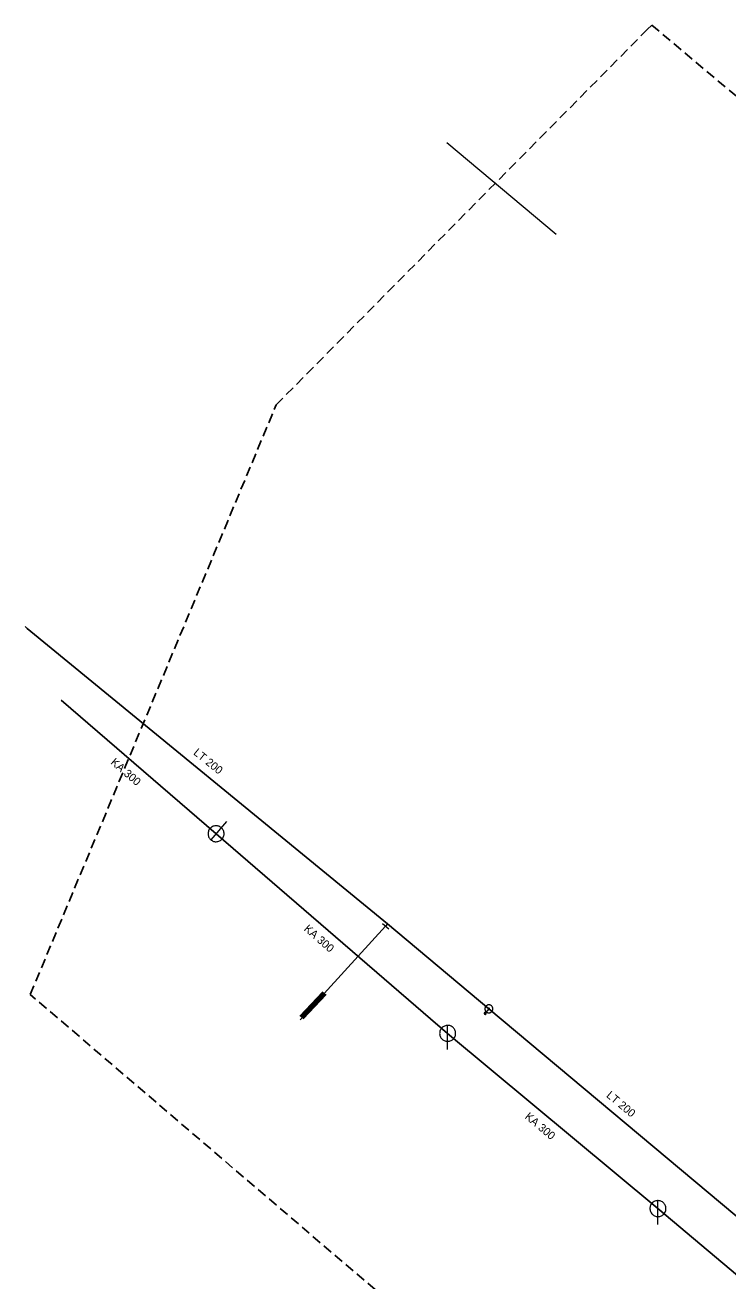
# Model space of a CAD drawing. Extents: x -790267 to -789874, y -989766 to -989454.
# Drawn here: x -790266.7 to -790179, y -989612.1 to -989455.1 of the extents above; entities that cross this region are included whole.
import ezdxf

# ---------------------------------------------------------------- set-up
doc = ezdxf.new("R2010")
doc.units = 0
doc.header["$LTSCALE"] = 0.4
doc.linetypes.add('MEDIUM_DASHED', pattern=[4.5, 3, -1.5])
doc.layers.add('1', color=7, linetype='Continuous')
for name, color, linetype, lineweight in [('13', 7, 'Continuous', 13), ('14', 7, 'Continuous', 13), ('17', 7, 'Continuous', 25), ('22', 7, 'Continuous', 13), ('3', 7, 'Continuous', 106), ('34', 7, 'Continuous', 13), ('47', 7, 'Continuous', 13), ('63', 7, 'MEDIUM_DASHED', 25), ('9', 7, 'Continuous', 13)]:
    doc.layers.add(name, color=color, linetype=linetype, lineweight=lineweight)

msp = doc.modelspace()

# ---------------------------------------------------------------- linework, layer by layer
at = {"layer": '13'}
for p, q in [((-790214.037, -989469.794), (-790200.396, -989481.26)), ((-790221.697, -989567.736), (-790232.379, -989579.425))]:
    msp.add_line(p, q, dxfattribs=at)
at = {"layer": '14'}
for p, q in [((-790221.46, -989567.445), (-790221.697, -989567.736)), ((-790208.807, -989578.056), (-790209.259, -989578.62))]:
    msp.add_line(p, q, dxfattribs=at)
at = {"layer": '14', "lineweight": 25}
msp.add_line((-790187.694, -989603.019), (-790213.954, -989581.125), dxfattribs=at)
for points in [[(-790213.954, -989581.125), (-790242.87, -989556.179), (-790262.214, -989539.492)], [(-790061.947, -989710.475), (-790095.515, -989680.27), (-790099.671, -989676.98), (-790135.954, -989646.924), (-790158.92, -989627.239), (-790187.694, -989603.019)]]:
    msp.add_lwpolyline(points, dxfattribs=at)
at = {"layer": '17'}
msp.add_line((-790208.807, -989578.056), (-790176.305, -989605.314), dxfattribs=at)
msp.add_lwpolyline([(-790266.706, -989530.283), (-790266.449, -989530.55), (-790221.46, -989567.445), (-790208.807, -989578.056)], dxfattribs=at)
at = {"layer": '22'}
for p, q in [((-790241.563, -989554.664), (-790243.522, -989556.935)), ((-790213.954, -989583.125), (-790213.953, -989580.125)), ((-790187.694, -989605.019), (-790187.693, -989602.019))]:
    msp.add_line(p, q, dxfattribs=at)
for points in [[(-790243.626, -989555.525), (-790243.693, -989555.611), (-790243.75, -989555.705), (-790243.796, -989555.805), (-790243.832, -989555.907), (-790243.856, -989556.015), (-790243.868, -989556.123), (-790243.868, -989556.233), (-790243.855, -989556.342), (-790243.832, -989556.449), (-790243.797, -989556.552), (-790243.75, -989556.651), (-790243.692, -989556.745), (-790243.626, -989556.832), (-790243.55, -989556.91), (-790243.465, -989556.981), (-790243.374, -989557.041), (-790243.277, -989557.092), (-790243.175, -989557.131), (-790243.068, -989557.158), (-790242.961, -989557.174), (-790242.851, -989557.178), (-790242.742, -989557.17), (-790242.634, -989557.15), (-790242.529, -989557.119), (-790242.429, -989557.076), (-790242.333, -989557.022), (-790242.244, -989556.958), (-790242.163, -989556.885), (-790242.089, -989556.803), (-790242.026, -989556.714), (-790241.972, -989556.62), (-790241.929, -989556.519), (-790241.897, -989556.414), (-790241.877, -989556.306), (-790241.87, -989556.197), (-790241.873, -989556.088), (-790241.889, -989555.979), (-790241.917, -989555.873), (-790241.955, -989555.771), (-790242.006, -989555.673), (-790242.066, -989555.582), (-790242.136, -989555.498), (-790242.215, -989555.422), (-790242.302, -989555.355), (-790242.395, -989555.298), (-790242.494, -989555.251), (-790242.598, -989555.216), (-790242.705, -989555.192), (-790242.814, -989555.18), (-790242.923, -989555.18), (-790243.032, -989555.191), (-790243.139, -989555.215), (-790243.242, -989555.25), (-790243.341, -989555.297), (-790243.435, -989555.353), (-790243.522, -989555.421), (-790243.601, -989555.497)], [(-790212.954, -989581.125), (-790212.959, -989581.016), (-790212.977, -989580.908), (-790213.007, -989580.802), (-790213.047, -989580.701), (-790213.099, -989580.604), (-790213.161, -989580.514), (-790213.233, -989580.431), (-790213.313, -989580.357), (-790213.401, -989580.291), (-790213.495, -989580.236), (-790213.595, -989580.191), (-790213.7, -989580.158), (-790213.807, -989580.136), (-790213.916, -989580.126), (-790214.026, -989580.128), (-790214.134, -989580.142), (-790214.241, -989580.167), (-790214.344, -989580.204), (-790214.442, -989580.253), (-790214.534, -989580.311), (-790214.62, -989580.38), (-790214.697, -989580.457), (-790214.766, -989580.543), (-790214.825, -989580.635), (-790214.873, -989580.733), (-790214.91, -989580.836), (-790214.936, -989580.943), (-790214.95, -989581.051), (-790214.953, -989581.161), (-790214.943, -989581.27), (-790214.922, -989581.377), (-790214.888, -989581.481), (-790214.844, -989581.581), (-790214.789, -989581.676), (-790214.723, -989581.764), (-790214.649, -989581.844), (-790214.566, -989581.916), (-790214.476, -989581.978), (-790214.38, -989582.03), (-790214.278, -989582.071), (-790214.173, -989582.101), (-790214.065, -989582.119), (-790213.955, -989582.125), (-790213.846, -989582.119), (-790213.738, -989582.101), (-790213.633, -989582.072), (-790213.531, -989582.031), (-790213.434, -989581.979), (-790213.344, -989581.917), (-790213.261, -989581.846), (-790213.186, -989581.766), (-790213.121, -989581.678), (-790213.065, -989581.584), (-790213.021, -989581.484), (-790212.987, -989581.38), (-790212.965, -989581.272), (-790212.955, -989581.163)], [(-790186.694, -989603.019), (-790186.699, -989602.91), (-790186.717, -989602.802), (-790186.747, -989602.696), (-790186.787, -989602.595), (-790186.839, -989602.498), (-790186.901, -989602.408), (-790186.973, -989602.325), (-790187.053, -989602.251), (-790187.141, -989602.185), (-790187.235, -989602.13), (-790187.335, -989602.085), (-790187.44, -989602.052), (-790187.547, -989602.03), (-790187.656, -989602.02), (-790187.766, -989602.022), (-790187.874, -989602.036), (-790187.981, -989602.061), (-790188.084, -989602.098), (-790188.182, -989602.147), (-790188.274, -989602.205), (-790188.36, -989602.274), (-790188.437, -989602.351), (-790188.506, -989602.437), (-790188.565, -989602.529), (-790188.613, -989602.627), (-790188.65, -989602.73), (-790188.676, -989602.837), (-790188.69, -989602.945), (-790188.693, -989603.055), (-790188.683, -989603.164), (-790188.662, -989603.271), (-790188.628, -989603.375), (-790188.584, -989603.475), (-790188.529, -989603.57), (-790188.463, -989603.658), (-790188.389, -989603.738), (-790188.306, -989603.81), (-790188.216, -989603.872), (-790188.12, -989603.924), (-790188.018, -989603.965), (-790187.913, -989603.995), (-790187.805, -989604.013), (-790187.695, -989604.019), (-790187.586, -989604.013), (-790187.478, -989603.995), (-790187.373, -989603.966), (-790187.271, -989603.925), (-790187.174, -989603.873), (-790187.084, -989603.811), (-790187.001, -989603.74), (-790186.926, -989603.66), (-790186.861, -989603.572), (-790186.805, -989603.478), (-790186.761, -989603.378), (-790186.727, -989603.274), (-790186.705, -989603.166), (-790186.695, -989603.057)]]:
    msp.add_lwpolyline(points, close=True, dxfattribs=at)
at = {"layer": '3'}
msp.add_line((-790229.329, -989576.088), (-790232.2, -989579.14), dxfattribs=at)
at = {"layer": '3', "lineweight": 100}
msp.add_line((-790229.329, -989576.088), (-790232.2, -989579.14), dxfattribs=at)
at = {"layer": '34'}
msp.add_line((-790222.078, -989567.412), (-790221.316, -989568.06), dxfattribs=at)
at = {"layer": '47'}
for points in [[(-790208.419, -989578.372), (-790208.389, -989578.329), (-790208.362, -989578.284), (-790208.341, -989578.237), (-790208.324, -989578.187), (-790208.313, -989578.136), (-790208.308, -989578.083), (-790208.308, -989578.031), (-790208.313, -989577.979), (-790208.323, -989577.928), (-790208.339, -989577.878), (-790208.36, -989577.83), (-790208.387, -989577.785), (-790208.417, -989577.742), (-790208.452, -989577.703), (-790208.49, -989577.668), (-790208.533, -989577.638), (-790208.578, -989577.611), (-790208.626, -989577.589), (-790208.675, -989577.573), (-790208.726, -989577.562), (-790208.779, -989577.557), (-790208.831, -989577.556), (-790208.884, -989577.562), (-790208.934, -989577.572), (-790208.984, -989577.588), (-790209.032, -989577.609), (-790209.078, -989577.635), (-790209.12, -989577.666), (-790209.159, -989577.701), (-790209.194, -989577.739), (-790209.224, -989577.782), (-790209.251, -989577.827), (-790209.273, -989577.875), (-790209.289, -989577.924), (-790209.3, -989577.975), (-790209.306, -989578.027), (-790209.307, -989578.08), (-790209.301, -989578.132), (-790209.29, -989578.183), (-790209.274, -989578.233), (-790209.253, -989578.281), (-790209.228, -989578.326), (-790209.196, -989578.369), (-790209.161, -989578.408), (-790209.123, -989578.443), (-790209.08, -989578.473), (-790209.035, -989578.5), (-790208.988, -989578.522), (-790208.938, -989578.538), (-790208.887, -989578.549), (-790208.835, -989578.555), (-790208.783, -989578.555), (-790208.731, -989578.55), (-790208.679, -989578.539), (-790208.629, -989578.523), (-790208.581, -989578.502), (-790208.537, -989578.476), (-790208.493, -989578.445), (-790208.454, -989578.41)], [(-790208.743, -989578.107), (-790208.737, -989578.1), (-790208.734, -989578.093), (-790208.73, -989578.085), (-790208.728, -989578.077), (-790208.726, -989578.069), (-790208.725, -989578.06), (-790208.724, -989578.051), (-790208.725, -989578.043), (-790208.728, -989578.035), (-790208.73, -989578.026), (-790208.734, -989578.018), (-790208.738, -989578.011), (-790208.743, -989578.004), (-790208.748, -989577.998), (-790208.755, -989577.992), (-790208.762, -989577.986), (-790208.769, -989577.983), (-790208.777, -989577.979), (-790208.785, -989577.977), (-790208.793, -989577.975), (-790208.802, -989577.974), (-790208.811, -989577.973), (-790208.819, -989577.974), (-790208.828, -989577.976), (-790208.836, -989577.979), (-790208.844, -989577.983), (-790208.851, -989577.987), (-790208.858, -989577.992), (-790208.864, -989577.997), (-790208.87, -989578.004), (-790208.876, -989578.011), (-790208.879, -989578.018), (-790208.883, -989578.026), (-790208.885, -989578.034), (-790208.887, -989578.042), (-790208.889, -989578.05), (-790208.889, -989578.06), (-790208.888, -989578.068), (-790208.886, -989578.077), (-790208.883, -989578.085), (-790208.879, -989578.093), (-790208.875, -989578.1), (-790208.87, -989578.107), (-790208.865, -989578.113), (-790208.858, -989578.119), (-790208.851, -989578.125), (-790208.844, -989578.128), (-790208.836, -989578.132), (-790208.828, -989578.134), (-790208.82, -989578.136), (-790208.812, -989578.138), (-790208.802, -989578.138), (-790208.794, -989578.137), (-790208.786, -989578.134), (-790208.777, -989578.132), (-790208.769, -989578.128), (-790208.762, -989578.124), (-790208.755, -989578.119), (-790208.749, -989578.114)]]:
    msp.add_lwpolyline(points, close=True, dxfattribs=at)
at = {"layer": '63'}
msp.add_lwpolyline([(-790188.469, -989455.136), (-790139.344, -989496.446), (-790139.344, -989496.446), (-790029.929, -989518.217), (-790029.929, -989518.217), (-789963.498, -989555.061), (-789963.498, -989555.061), (-789946.75, -989559.527), (-789946.75, -989559.527), (-789908.79, -989634.89), (-789908.79, -989634.89), (-790051.142, -989765.519), (-790051.142, -989765.519), (-790157.208, -989714.719), (-790157.208, -989714.719), (-790153.3, -989672.851), (-790153.3, -989672.851), (-790266.065, -989576.274), (-790266.065, -989576.274), (-790235.362, -989502.586), (-790235.362, -989502.586), (-790189.028, -989455.694), (-790189.028, -989455.694)], close=True, dxfattribs=at)
at = {"layer": '9'}
for points in [[(-790209.385, -989578.62), (-790209.385, -989578.633), (-790209.382, -989578.646), (-790209.38, -989578.659), (-790209.375, -989578.671), (-790209.369, -989578.683), (-790209.362, -989578.694), (-790209.353, -989578.704), (-790209.343, -989578.714), (-790209.333, -989578.722), (-790209.323, -989578.729), (-790209.311, -989578.735), (-790209.299, -989578.74), (-790209.286, -989578.743), (-790209.272, -989578.745), (-790209.26, -989578.747), (-790209.247, -989578.746), (-790209.233, -989578.744), (-790209.221, -989578.741), (-790209.208, -989578.736), (-790209.196, -989578.73), (-790209.186, -989578.723), (-790209.176, -989578.715), (-790209.166, -989578.705), (-790209.157, -989578.695), (-790209.151, -989578.684), (-790209.145, -989578.672), (-790209.14, -989578.66), (-790209.137, -989578.647), (-790209.135, -989578.634), (-790209.132, -989578.621), (-790209.134, -989578.608), (-790209.136, -989578.595), (-790209.139, -989578.582), (-790209.144, -989578.57), (-790209.149, -989578.558), (-790209.157, -989578.547), (-790209.164, -989578.537), (-790209.174, -989578.527), (-790209.184, -989578.519), (-790209.196, -989578.512), (-790209.208, -989578.506), (-790209.22, -989578.501), (-790209.233, -989578.498), (-790209.245, -989578.496), (-790209.259, -989578.495), (-790209.272, -989578.495), (-790209.284, -989578.497), (-790209.298, -989578.5), (-790209.309, -989578.505), (-790209.321, -989578.511), (-790209.333, -989578.518), (-790209.343, -989578.526), (-790209.353, -989578.536), (-790209.36, -989578.546), (-790209.368, -989578.557), (-790209.374, -989578.569), (-790209.379, -989578.581), (-790209.382, -989578.594), (-790209.384, -989578.607)], [(-790209.365, -989578.62), (-790209.365, -989578.631), (-790209.364, -989578.642), (-790209.36, -989578.653), (-790209.357, -989578.663), (-790209.352, -989578.673), (-790209.346, -989578.682), (-790209.338, -989578.691), (-790209.331, -989578.699), (-790209.321, -989578.706), (-790209.313, -989578.712), (-790209.303, -989578.717), (-790209.293, -989578.721), (-790209.282, -989578.724), (-790209.271, -989578.727), (-790209.26, -989578.727), (-790209.249, -989578.727), (-790209.238, -989578.725), (-790209.227, -989578.722), (-790209.217, -989578.718), (-790209.206, -989578.713), (-790209.198, -989578.707), (-790209.189, -989578.7), (-790209.181, -989578.692), (-790209.174, -989578.683), (-790209.168, -989578.674), (-790209.163, -989578.664), (-790209.159, -989578.654), (-790209.156, -989578.643), (-790209.154, -989578.632), (-790209.152, -989578.621), (-790209.152, -989578.61), (-790209.154, -989578.599), (-790209.157, -989578.588), (-790209.162, -989578.578), (-790209.167, -989578.568), (-790209.173, -989578.559), (-790209.179, -989578.55), (-790209.188, -989578.542), (-790209.196, -989578.535), (-790209.206, -989578.529), (-790209.216, -989578.524), (-790209.225, -989578.52), (-790209.237, -989578.517), (-790209.247, -989578.515), (-790209.259, -989578.515), (-790209.27, -989578.514), (-790209.281, -989578.516), (-790209.292, -989578.519), (-790209.301, -989578.523), (-790209.311, -989578.528), (-790209.321, -989578.534), (-790209.33, -989578.541), (-790209.338, -989578.549), (-790209.345, -989578.558), (-790209.35, -989578.567), (-790209.355, -989578.577), (-790209.36, -989578.587), (-790209.363, -989578.598), (-790209.365, -989578.609)], [(-790209.346, -989578.62), (-790209.346, -989578.629), (-790209.345, -989578.638), (-790209.342, -989578.647), (-790209.338, -989578.655), (-790209.335, -989578.663), (-790209.33, -989578.671), (-790209.323, -989578.678), (-790209.318, -989578.684), (-790209.311, -989578.69), (-790209.303, -989578.695), (-790209.294, -989578.699), (-790209.287, -989578.702), (-790209.277, -989578.705), (-790209.269, -989578.706), (-790209.26, -989578.708), (-790209.25, -989578.707), (-790209.242, -989578.706), (-790209.233, -989578.703), (-790209.225, -989578.7), (-790209.217, -989578.696), (-790209.208, -989578.691), (-790209.201, -989578.685), (-790209.196, -989578.679), (-790209.19, -989578.672), (-790209.184, -989578.664), (-790209.181, -989578.656), (-790209.178, -989578.648), (-790209.174, -989578.639), (-790209.174, -989578.63), (-790209.171, -989578.621), (-790209.173, -989578.612), (-790209.174, -989578.603), (-790209.176, -989578.594), (-790209.179, -989578.586), (-790209.184, -989578.578), (-790209.189, -989578.57), (-790209.195, -989578.563), (-790209.201, -989578.557), (-790209.208, -989578.551), (-790209.216, -989578.546), (-790209.223, -989578.542), (-790209.232, -989578.539), (-790209.24, -989578.536), (-790209.25, -989578.535), (-790209.259, -989578.534), (-790209.267, -989578.534), (-790209.277, -989578.535), (-790209.286, -989578.538), (-790209.294, -989578.541), (-790209.301, -989578.545), (-790209.309, -989578.55), (-790209.316, -989578.556), (-790209.323, -989578.562), (-790209.328, -989578.569), (-790209.333, -989578.577), (-790209.338, -989578.585), (-790209.341, -989578.593), (-790209.343, -989578.602), (-790209.345, -989578.611)], [(-790209.326, -989578.62), (-790209.326, -989578.627), (-790209.325, -989578.634), (-790209.323, -989578.641), (-790209.321, -989578.647), (-790209.318, -989578.653), (-790209.314, -989578.659), (-790209.309, -989578.665), (-790209.304, -989578.67), (-790209.299, -989578.674), (-790209.293, -989578.678), (-790209.287, -989578.681), (-790209.281, -989578.684), (-790209.274, -989578.685), (-790209.267, -989578.688), (-790209.26, -989578.688), (-790209.252, -989578.688), (-790209.245, -989578.686), (-790209.239, -989578.685), (-790209.233, -989578.682), (-790209.225, -989578.679), (-790209.221, -989578.675), (-790209.215, -989578.671), (-790209.21, -989578.666), (-790209.206, -989578.66), (-790209.201, -989578.654), (-790209.198, -989578.648), (-790209.196, -989578.642), (-790209.194, -989578.635), (-790209.193, -989578.628), (-790209.191, -989578.621), (-790209.191, -989578.614), (-790209.193, -989578.607), (-790209.195, -989578.6), (-790209.198, -989578.594), (-790209.201, -989578.587), (-790209.205, -989578.582), (-790209.208, -989578.576), (-790209.213, -989578.571), (-790209.22, -989578.567), (-790209.225, -989578.563), (-790209.232, -989578.56), (-790209.238, -989578.557), (-790209.245, -989578.555), (-790209.252, -989578.554), (-790209.259, -989578.554), (-790209.266, -989578.554), (-790209.272, -989578.554), (-790209.279, -989578.556), (-790209.286, -989578.559), (-790209.292, -989578.562), (-790209.298, -989578.566), (-790209.304, -989578.57), (-790209.309, -989578.575), (-790209.313, -989578.581), (-790209.316, -989578.586), (-790209.32, -989578.593), (-790209.323, -989578.599), (-790209.323, -989578.606), (-790209.326, -989578.613)], [(-790209.306, -989578.62), (-790209.306, -989578.625), (-790209.306, -989578.63), (-790209.304, -989578.635), (-790209.303, -989578.639), (-790209.301, -989578.644), (-790209.298, -989578.648), (-790209.294, -989578.651), (-790209.291, -989578.655), (-790209.288, -989578.658), (-790209.284, -989578.661), (-790209.279, -989578.663), (-790209.274, -989578.665), (-790209.27, -989578.666), (-790209.265, -989578.668), (-790209.26, -989578.668), (-790209.255, -989578.668), (-790209.25, -989578.667), (-790209.245, -989578.666), (-790209.24, -989578.664), (-790209.235, -989578.662), (-790209.232, -989578.659), (-790209.228, -989578.656), (-790209.225, -989578.652), (-790209.222, -989578.649), (-790209.218, -989578.645), (-790209.217, -989578.64), (-790209.215, -989578.636), (-790209.213, -989578.631), (-790209.213, -989578.626), (-790209.212, -989578.621), (-790209.212, -989578.616), (-790209.213, -989578.611), (-790209.213, -989578.606), (-790209.216, -989578.602), (-790209.218, -989578.597), (-790209.221, -989578.593), (-790209.223, -989578.589), (-790209.227, -989578.586), (-790209.23, -989578.583), (-790209.235, -989578.58), (-790209.24, -989578.578), (-790209.244, -989578.576), (-790209.249, -989578.575), (-790209.254, -989578.574), (-790209.259, -989578.574), (-790209.264, -989578.574), (-790209.269, -989578.575), (-790209.274, -989578.575), (-790209.277, -989578.577), (-790209.282, -989578.579), (-790209.287, -989578.582), (-790209.289, -989578.585), (-790209.294, -989578.588), (-790209.296, -989578.592), (-790209.299, -989578.596), (-790209.301, -989578.601), (-790209.304, -989578.605), (-790209.304, -989578.61), (-790209.306, -989578.615)], [(-790209.286, -989578.62), (-790209.286, -989578.623), (-790209.287, -989578.626), (-790209.286, -989578.628), (-790209.284, -989578.631), (-790209.284, -989578.634), (-790209.282, -989578.636), (-790209.279, -989578.638), (-790209.277, -989578.64), (-790209.276, -989578.642), (-790209.274, -989578.644), (-790209.271, -989578.646), (-790209.267, -989578.647), (-790209.266, -989578.647), (-790209.262, -989578.648), (-790209.26, -989578.648), (-790209.257, -989578.648), (-790209.254, -989578.648), (-790209.25, -989578.647), (-790209.249, -989578.646), (-790209.245, -989578.645), (-790209.244, -989578.643), (-790209.24, -989578.641), (-790209.239, -989578.639), (-790209.238, -989578.637), (-790209.235, -989578.635), (-790209.235, -989578.632), (-790209.233, -989578.629), (-790209.233, -989578.627), (-790209.232, -989578.624), (-790209.23, -989578.621), (-790209.232, -989578.618), (-790209.232, -989578.615), (-790209.233, -989578.612), (-790209.233, -989578.61), (-790209.235, -989578.607), (-790209.237, -989578.605), (-790209.238, -989578.602), (-790209.24, -989578.6), (-790209.243, -989578.599), (-790209.245, -989578.597), (-790209.247, -989578.596), (-790209.25, -989578.595), (-790209.252, -989578.594), (-790209.255, -989578.594), (-790209.259, -989578.593), (-790209.262, -989578.594), (-790209.265, -989578.593), (-790209.267, -989578.595), (-790209.27, -989578.595), (-790209.272, -989578.596), (-790209.274, -989578.598), (-790209.277, -989578.599), (-790209.279, -989578.601), (-790209.281, -989578.604), (-790209.282, -989578.606), (-790209.284, -989578.609), (-790209.284, -989578.611), (-790209.286, -989578.614), (-790209.286, -989578.617)], [(-790209.267, -989578.62), (-790209.267, -989578.622), (-790209.267, -989578.622), (-790209.266, -989578.622), (-790209.266, -989578.624), (-790209.267, -989578.625), (-790209.265, -989578.625), (-790209.265, -989578.625), (-790209.265, -989578.627), (-790209.265, -989578.627), (-790209.264, -989578.628), (-790209.262, -989578.628), (-790209.262, -989578.628), (-790209.262, -989578.629), (-790209.26, -989578.629), (-790209.26, -989578.629), (-790209.259, -989578.629), (-790209.257, -989578.629), (-790209.257, -989578.628), (-790209.257, -989578.628), (-790209.255, -989578.628), (-790209.255, -989578.627), (-790209.255, -989578.627), (-790209.254, -989578.626), (-790209.254, -989578.626), (-790209.252, -989578.625), (-790209.252, -989578.624), (-790209.25, -989578.623), (-790209.25, -989578.623), (-790209.25, -989578.622), (-790209.25, -989578.621), (-790209.25, -989578.62), (-790209.25, -989578.619), (-790209.25, -989578.619), (-790209.252, -989578.618), (-790209.252, -989578.617), (-790209.252, -989578.616), (-790209.252, -989578.616), (-790209.254, -989578.615), (-790209.254, -989578.615), (-790209.255, -989578.614), (-790209.255, -989578.614), (-790209.257, -989578.613), (-790209.257, -989578.613), (-790209.257, -989578.613), (-790209.259, -989578.613), (-790209.26, -989578.613), (-790209.261, -989578.613), (-790209.261, -989578.613), (-790209.262, -989578.614), (-790209.262, -989578.613), (-790209.264, -989578.615), (-790209.264, -989578.615), (-790209.265, -989578.615), (-790209.265, -989578.615), (-790209.266, -989578.617), (-790209.266, -989578.618), (-790209.266, -989578.619), (-790209.267, -989578.619), (-790209.267, -989578.62)]]:
    msp.add_lwpolyline(points, close=True, dxfattribs=at)

# ---------------------------------------------------------------- texts
at = {"layer": '1'}
for s, rotation, p in [('KA 300', 319, (-790256.11, -989547.379)), ('LT 200', 321, (-790245.775, -989546.198)), ('KA 300', 319, (-790231.98, -989568.196)), ('LT 200', 320, (-790194.221, -989589.002)), ('KA 300', 320, (-790204.399, -989591.675))]:
    msp.add_text(s, height=1, rotation=rotation, dxfattribs=at).set_placement(p)

doc.saveas('drawing.dxf')
